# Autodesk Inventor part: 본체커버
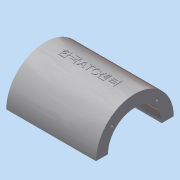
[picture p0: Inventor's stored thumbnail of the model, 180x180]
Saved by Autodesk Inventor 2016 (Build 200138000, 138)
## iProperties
Created: 2015-12
Part Number: 본체커버
Material: 알루미늄 6061
Document SubType Name: Modeling
Designer: mduedu
Density: 2.71 g/cm^3
Mass: 174.994 g
Surface Area: 167.085 cm^2
Volume: 64.5736 cm^3
Appearance: 알루미늄 - 평지
Author: mduedu
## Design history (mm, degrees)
sketch "스케치1"
  geometry: L1 (45, 40)-(-45, 40); L2 (-45, 40)-(-45, -40); L3 (-45, -40)-(45, -40); L4 (45, -40)-(45, 40); L5 (45, 40)-(-45, -40); L6 (-45, 40)-(45, -40); 1 further point
  constraints: 12 end point, 2 midpoint, 2 parallel, 1 horizontal, 1 perpendicular
  dimensions: "d0" = 90 distance of L2.end L3.end; "d2" = 80 distance of L1.end L2.end
extrude "돌출1" new body sketch "스케치1" distance "d3" = 10; taper "d4" = 0 deg
sketch "스케치2"
  geometry: L1 (0, 40)-(0, -40) reference; C1 r 32.5 at (80, 0); 1 further point
  constraints: 1 centre point
  dimensions: "d5" = 65 diameter of C1; "d6" = 80 distance from line of C1.centre L1
extrude "돌출2" join sketch "스케치2" stored distance "d7" = 75; taper "d8" = 0 deg
sketch "스케치3"
  geometry: L1 (-27.5, -20)-(27.5, -20); L2 (27.5, -20)-(27.5, 20); L3 (27.5, 20)-(-27.5, 20); L4 (-27.5, 20)-(-27.5, -20); L5 (-27.5, -20)-(27.5, 20); L6 (27.5, -20)-(-27.5, 20); 1 further point
  constraints: 12 end point, 2 midpoint, 2 parallel, 1 horizontal, 1 perpendicular
  dimensions: "d9" = 55 distance of L2.end L3.end; "d11" = 40 distance of L1.end L2.end
extrude "돌출3" new body sketch "스케치3" stored distance "d12" = 75; taper "d13" = 0 deg
fillet "모깎기1"
fillet "모깎기2"
feature "결합1"
  node "솔리드2"
fillet "모깎기3" dims "d14" = 10
sketch "스케치4"
  geometry: L1 (-37.5, 47.5)-(37.5, 47.5) reference; L2 (35, 10)-(45, 10) reference; L3 (32.5, 47.5)-(40, 10); L4 (37.5, 47.5)-(37.5, 112.5) reference; L5 (45, 10)-(45, 0) reference; 1 further point
  constraints: 2 end point, 1 midpoint, 1 point on line
  dimensions: "d15" = 5 distance from line of L3.start L4; "d16" = 5 distance from line of L3.end L5
sketch "스케치5"
  geometry: L1 (10, 40)-(10, 30) reference; L2 (10, 35)-(56.569, 22.522); L3 (0, 40)-(10, 40) reference; 2 further points
  constraints: 2 end point, 1 midpoint, 2 other
  dimensions: "d17" = 5 distance from line of L2.start L3; "d18" = 15 deg angle of L2 L3
feature "리브1" dims "d19" = 1, "d20" = 6, "d21" = 0, "d22" = 0, "d23" = 1, "d24" = 1
feature "리브2" dims "d25" = 1, "d26" = 6, "d27" = 0, "d28" = 0, "d29" = 1, "d30" = 1
fillet "모깎기4" dims "d31" = 2
fillet "모깎기5" dims "d32" = 2
fillet "모깎기6" dims "d33" = 2
sketch "스케치6"
  geometry: A1 r 10 centre (-35, 30) between (-35, 40) and (-45, 30) reference; A2 r 10 centre (35, 30) between (45, 30) and (35, 40) reference; A3 r 10 centre (35, -30) between (35, -40) and (45, -30) reference; A4 r 10 centre (-35, -30) between (-45, -30) and (-35, -40) reference; 5 further points
  constraints: 4 coincident
hole "구멍1" sketch "스케치6" at (-35, 30), (35, 30), (35, -30), (-35, -30) diameter "d34" = 7; stored, may be unused: countersink angle "d38" = 90 deg, drill point angle "d40" = 118 deg; dims "d35" = 6, "d36" = 12, "d37" = 3, "d39" = 8
fillet "모깎기7" dims "d41" = 2
hole "구멍2" diameter "d44" = 45; stored, may be unused: countersink angle "d48" = 90 deg, drill point angle "d50" = 118 deg; dims "d42" = 10, "d43" = 10, "d45" = 6, "d46" = 4, "d47" = 2, "d49" = 8
sketch "스케치7" dims "d52" = 26.5
  geometry: L1 (0, 0)-(32.5, 0); L2 (0, 0)-(22.981, 22.981); A1 r 32.5 centre (0, 0) between (32.5, 0) and (22.981, 22.981) reference; 3 further points
  constraints: 4 end point, 2 point on circle, 1 coincident, 1 horizontal, 1 point on line, 3 other
  dimensions: "d51" = 45 deg angle of L2 L1
hole "구멍3" sketch "스케치7" at (18.738, 18.738) diameter "d54" = 2.459; stored, may be unused: countersink angle "d58" = 90 deg, drill point angle "d60" = 118 deg; dims "d55" = 8, "d56" = 4, "d57" = 2, "d59" = 10
sketch "스케치13"
  geometry: L1 (-45, 80)-(105, 80); L2 (105, 80)-(105, -30); L3 (105, -30)-(-45, -30); L4 (-45, -30)-(-45, 80); L5 (0, 0)-(60, 0) reference; C1 r 32.5 at (30, 80) reference; 1 further point
  constraints: 8 end point, 2 parallel, 1 coincident, 1 horizontal, 1 midpoint, 1 perpendicular
  dimensions: "d99" = 30 distance between parallel lines of L3 L5; "d126" = 150 distance between parallel lines of L2 L4
extrude "돌출8" cut sketch "스케치13" stored distance "d97" = 10; taper "d98" = 0 deg
node "작업 평면2"
sketch "스케치14"
  geometry: 2 further points
  constraints: 1 coincident, 1 other
feature "엠보싱1" sketch "스케치14" dims "d102" = 0.5, "d103" = 0
sketch "스케치18"
  geometry: L1 (0, -10)-(0, 0) reference; L2 (75, 0)-(75, -10) reference; L3 (0, -5)-(75, -5); C1 r 1.5 at (13, -5); 1 further point
  constraints: 2 end point, 2 midpoint, 1 centre point, 1 point on line
  dimensions: "d127" = 3 diameter of C1; "d128" = 13 distance from line of L1 C1.centre
extrude "돌출9" cut sketch "스케치18" distance "d129" = 2; taper "d130" = 0 deg
chamfer "모따기2" distance "d131" = 0.5; stored, may be unused: second distance "d132" = 2, angle "d133" = 45 deg
fillet "모깎기12" dims "d134" = 0.1
node "솔리드1"
mirror "대칭1"
mirror "대칭2"
pattern_circular "원형 패턴1" dims angle "d62" = 360 deg
mirror "대칭3"
mirror "대칭5"
mirror "대칭6"
